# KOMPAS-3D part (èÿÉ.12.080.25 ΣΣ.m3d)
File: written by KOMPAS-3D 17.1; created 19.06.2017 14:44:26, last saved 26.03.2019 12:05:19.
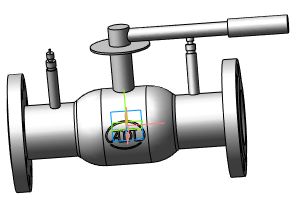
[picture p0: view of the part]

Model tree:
1. Операция без истории:2  (labels: Сталь 20  ГОСТ 1050-88)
